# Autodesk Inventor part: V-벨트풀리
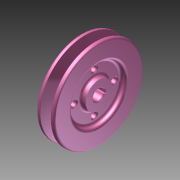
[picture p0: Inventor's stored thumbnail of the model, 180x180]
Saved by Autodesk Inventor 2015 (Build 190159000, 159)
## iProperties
Created: 2025-08
Part Number: V-벨트풀리
Material: 일반
Document SubType Name: Modeling
Designer: USER
Density: 1 g/cm^3
Appearance: 기본값
Author: USER
Author: jhkim
Creation Date: 2025-08-05
Sending System: Autodesk Inventor 2026
Preprocessor: ST-DEVELOPER v20.1
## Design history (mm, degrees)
node "V-벨트풀리1"
node "솔리드1"
node "기준1"
